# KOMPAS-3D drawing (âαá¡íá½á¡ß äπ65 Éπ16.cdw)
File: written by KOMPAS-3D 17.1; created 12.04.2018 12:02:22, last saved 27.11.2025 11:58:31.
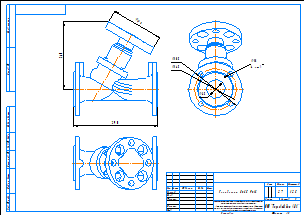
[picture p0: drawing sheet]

Sheet 1: A3, landscape

Title block, sheet 1: name: Гранбаланс Ду65 Ру16; material: Сталь 20  ГОСТ 1050-88; mass: 27; sheets: 1; sheet format: A3; stored path: C:\Users\kka\KOMPAS_Work\!Trash\КМ125 КМ127 КМ225Ф Двухходовые клапана\КМ125Ф + PSL\KOMPAS 2D\Гранрег КМ125Ф Ду32 Ру16.cdw

Views: Спереди 1, Спереди
Referenced files in C:\Users\mipv\Desktop\КБЧ\Имеющиеся\: Гранбаланс Ду65 Ру16  серия 10.m3d
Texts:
  kka
  adl
  Рама для чертежей
  Лит-Масса-Масштаб
  Материал-Предприятие
  Масштаб
  Изм.
  Лист
  № докум.
  Подп.
  Дата
  Лит.
  Разраб.
  Пров.
  Т.контр.
  Листов
  Внимание! Данный продукт является объектом авторского права ООО «Торговый Дом АДЛ».
  Запрещается изменение, копирование, распространение
  (в том числе путем копирования на другие сайты и ресурсы в Интернете)
  или любое иное использование информации и объектов без предварительного
  согласия правообладателя (ООО «Торговый Дом АДЛ»).
  Н.контр.
  Утв.
  ООО "Торговый дом АДЛ"
  Изменение
  Номер документа
  Подпись
  Обозначение документа
  Наименование изделия
  Масса изделия по ГОСТ 2.109-73
  Порядковый номер листа
  Общее количество листов в документе
  Характер работы, выполненной лицом, подписавшим документ
  Наименование или индекс предприятия, выпускающего документ
  Инв. № подл.
  Подп. и дата
  Взам. инв. №
  Инв. № дубл.
  Инвентарный номер подлинника по ГОСТ 2.501-68
  Подпись принявшего подлинник в отдел технической документации
  Инвентарный номер подлинника, взамен которого выпущен данный подлинник
  Инвентарный номер дубликата по ГОСТ 2.502-68
  Подпись принявшего дубликат в отдел технической документации
  Справ. №
  Перв. примен.
  Обозначение документа, взамен или на основании которого выпущен данный документ
  Обозначение документа, в котором впервые записан данный документ
  Подпись лица, копировавшего чертеж
  Обозначение формата листа
  !Рама для чертежа
Dimensions and other numbers on the sheet: 290; 240; 180; 1:2,5; 1; 27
